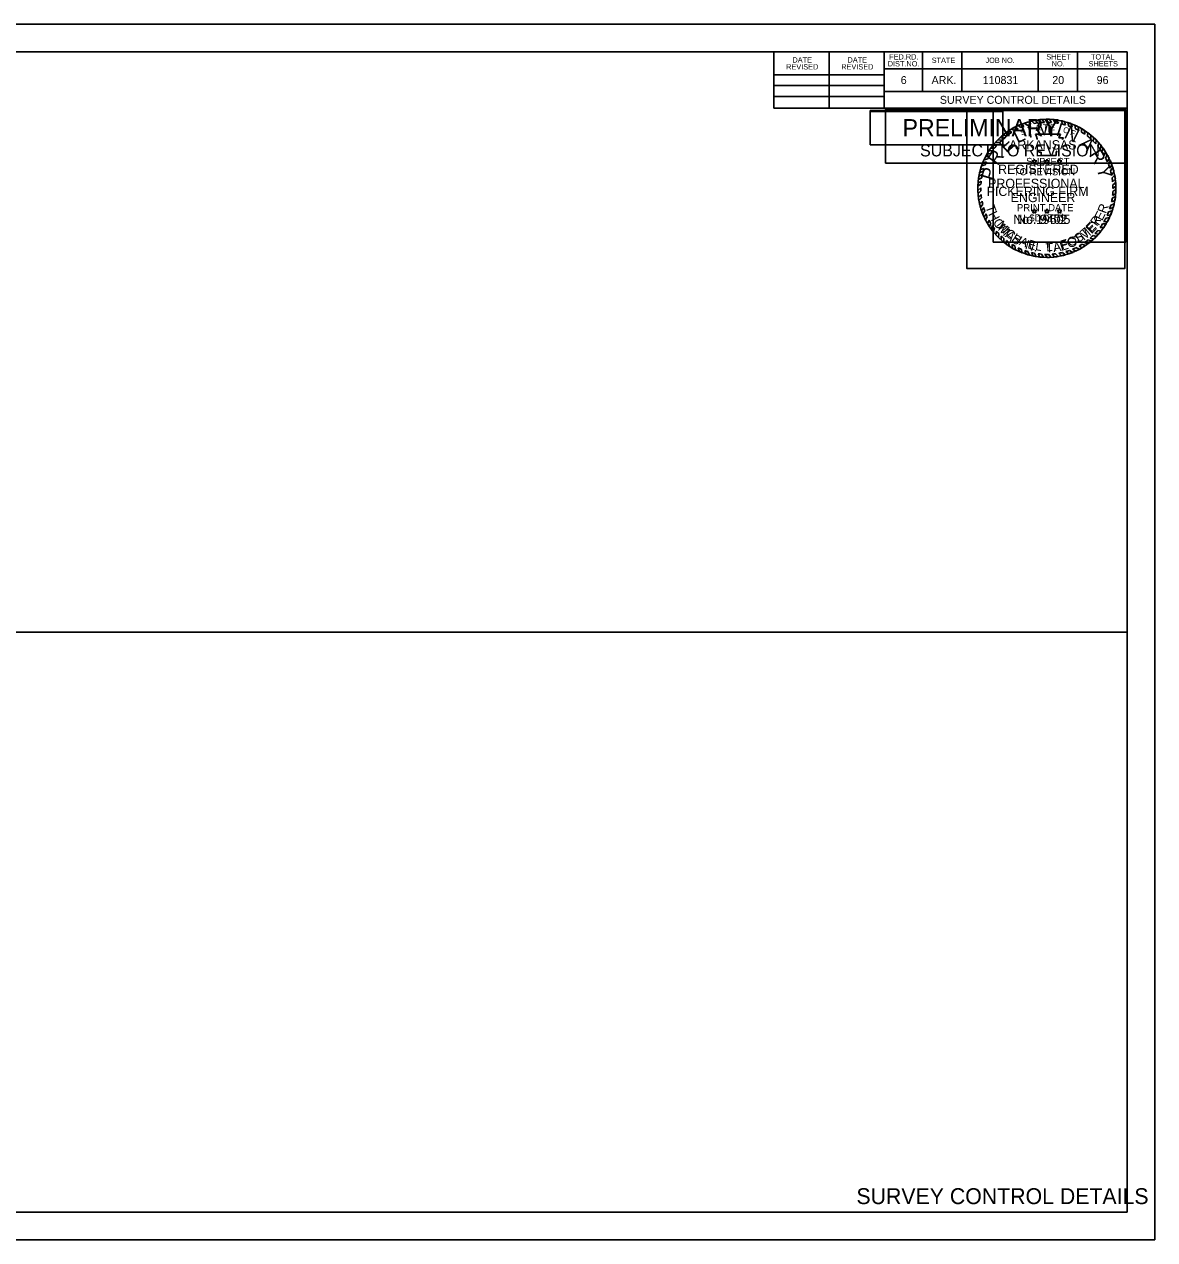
# Model space of a CAD drawing. Extents: x -0.29 to 1.42, y 0 to 0.92.
# Drawn here: x 0.564 to 1.417, y 0 to 0.917 of the extents above; entities that cross this region are included whole.
import ezdxf

# ---------------------------------------------------------------- set-up
doc = ezdxf.new("R2010")
doc.units = 0
for name, color, linetype in [('DSN_DRFT_Guideline-No-Plot', 7, 'Continuous'), ('SHET_Annotations', 7, 'Continuous'), ('SHET_Border-Lines', 7, 'Continuous'), ('SHET_Border-Text', 7, 'Continuous'), ('SHET_Stamp-Prelim', 7, 'Continuous'), ('SHET_Stamp-Seal', 7, 'Continuous'), ('STAMP_PE DIG SIG', 7, 'Continuous'), ('STAMP_PE_BACKGROUND', 7, 'Continuous'), ('STAMP_PE_FOSTER', 7, 'Continuous'), ('STAMP_PE_SEAL-INFO', 7, 'Continuous'), ('STAMP_PE_TAEGTMEYER', 7, 'Continuous'), ('STAMP_PRELIMINARY', 7, 'Continuous')]:
    doc.layers.add(name, color=color, linetype=linetype)

msp = doc.modelspace()

# ---------------------------------------------------------------- linework, layer by layer
at = {"layer": 'DSN_DRFT_Guideline-No-Plot'}
msp.add_lwpolyline([(0, 0), (1.41667, 0), (1.41667, 0.91667), (0, 0.91667)], close=True, dxfattribs=at)
at = {"layer": 'SHET_Border-Lines'}
for p, q in [((1.12962, 0.85338), (1.12962, 0.89583)), ((1.17114, 0.85338), (1.17114, 0.89583)), ((1.21266, 0.89583), (1.21266, 0.85338)), ((1.24173, 0.89583), (1.24173, 0.86601)), ((1.27123, 0.89583), (1.27123, 0.86601)), ((1.32894, 0.89583), (1.32894, 0.86601)), ((1.35843, 0.89583), (1.35843, 0.86601)), ((1.39583, 0.8832), (1.21266, 0.8832)), ((1.39583, 0.88329), (1.39583, 0.88329)), ((1.12962, 0.87856), (1.21266, 0.87856)), ((1.12962, 0.87057), (1.21266, 0.87057)), ((1.12962, 0.86223), (1.21266, 0.86223)), ((1.39583, 0.86601), (1.21266, 0.86601)), ((1.22524, 0.86601), (1.39583, 0.86601)), ((1.39583, 0.85338), (1.12962, 0.85338)), ((0.02083, 0.45833), (1.39583, 0.45833))]:
    msp.add_line(p, q, dxfattribs=at)
for points in [[(0.02083, 0.02083), (1.39583, 0.02083), (1.39583, 0.89583), (0.02083, 0.89583)], [(1.12962, 0.85338), (1.39583, 0.85338), (1.39583, 0.89583), (1.12962, 0.89583)]]:
    msp.add_lwpolyline(points, close=True, dxfattribs=at)
at = {"layer": 'SHET_Stamp-Prelim'}
msp.add_lwpolyline([(1.21366, 0.81193), (1.39483, 0.81193), (1.39483, 0.85238), (1.21366, 0.85238)], close=True, dxfattribs=at)
at = {"layer": 'SHET_Stamp-Seal'}
msp.add_line((1.34483, 0.80238), (1.34483, 0.80238), dxfattribs=at)
msp.add_lwpolyline([(1.29483, 0.75238), (1.39483, 0.75238), (1.39483, 0.85238), (1.29483, 0.85238)], close=True, dxfattribs=at)
at = {"layer": 'STAMP_PE DIG SIG'}
msp.add_lwpolyline([(1.20225, 0.85078), (1.30225, 0.85078), (1.30225, 0.82578), (1.20225, 0.82578)], close=True, dxfattribs=at)
at = {"layer": 'STAMP_PE_BACKGROUND'}
for points in [[(1.20225, 0.85171), (1.30225, 0.85171), (1.30225, 0.82578), (1.20225, 0.82578)], [(1.39417, 0.85171), (1.275, 0.85171), (1.275, 0.73255), (1.39417, 0.73255)]]:
    msp.add_lwpolyline(points, close=True, dxfattribs=at)
at = {"layer": 'STAMP_PE_SEAL-INFO'}
for p, q in [((1.3239, 0.84376), (1.32589, 0.84184)), ((1.32659, 0.8443), (1.32826, 0.84225)), ((1.32947, 0.84471), (1.33104, 0.84257)), ((1.33358, 0.84273), (1.33184, 0.84492)), ((1.33636, 0.84275), (1.33481, 0.84504)), ((1.33892, 0.84264), (1.33748, 0.84501)), ((1.34175, 0.84236), (1.34012, 0.84484)), ((1.34413, 0.84199), (1.34269, 0.84454)), ((1.34727, 0.84133), (1.3463, 0.8439)), ((1.34951, 0.84073), (1.34862, 0.84335)), ((1.30423, 0.83485), (1.30678, 0.8337)), ((1.30658, 0.83634), (1.30905, 0.83521)), ((1.30874, 0.8377), (1.31115, 0.83645)), ((1.31124, 0.8391), (1.31383, 0.83784)), ((1.31365, 0.84028), (1.31583, 0.83875)), ((1.31649, 0.84149), (1.31813, 0.83967)), ((1.31843, 0.8422), (1.32056, 0.84049)), ((1.32173, 0.84322), (1.32334, 0.84128)), ((1.35204, 0.83991), (1.35125, 0.84258)), ((1.35437, 0.83901), (1.35357, 0.84178)), ((1.35695, 0.83787), (1.35638, 0.84064)), ((1.35944, 0.83658), (1.35895, 0.83943)), ((1.36161, 0.83532), (1.36138, 0.83811)), ((1.36403, 0.83372), (1.36386, 0.8366)), ((1.36605, 0.83223), (1.36624, 0.83495)), ((1.2946, 0.82531), (1.29766, 0.82544)), ((1.29653, 0.82761), (1.29944, 0.8274)), ((1.29833, 0.82953), (1.30137, 0.8293)), ((1.3002, 0.83134), (1.30277, 0.83056)), ((1.30212, 0.83302), (1.30508, 0.83246)), ((1.32689, 0.8337), (1.34557, 0.8337)), ((1.32756, 0.83198), (1.32689, 0.8337)), ((1.32814, 0.83032), (1.32756, 0.83198)), ((1.32818, 0.82968), (1.32814, 0.83032)), ((1.34557, 0.8337), (1.34431, 0.83095)), ((1.34431, 0.83095), (1.34785, 0.83095)), ((1.34785, 0.83095), (1.34704, 0.82968)), ((1.36854, 0.83015), (1.36865, 0.83307)), ((1.37029, 0.82851), (1.37068, 0.8313)), ((1.37229, 0.82643), (1.37267, 0.82937)), ((1.37382, 0.82466), (1.37459, 0.82729)), ((1.37563, 0.82233), (1.37639, 0.82512)), ((1.28907, 0.81672), (1.29185, 0.81708)), ((1.29036, 0.81909), (1.29309, 0.8192)), ((1.29173, 0.82133), (1.29462, 0.82151)), ((1.29304, 0.82325), (1.29586, 0.82322)), ((1.32925, 0.82013), (1.32911, 0.82135)), ((1.33101, 0.82013), (1.32925, 0.82013)), ((1.33101, 0.81773), (1.33101, 0.82013)), ((1.34235, 0.81773), (1.33101, 0.81773)), ((1.34243, 0.81962), (1.34235, 0.81773)), ((1.34287, 0.82135), (1.34243, 0.81962)), ((1.37686, 0.82057), (1.37786, 0.82316)), ((1.37858, 0.81779), (1.3796, 0.82053)), ((1.3797, 0.81574), (1.38096, 0.81822)), ((1.28527, 0.80705), (1.28794, 0.80799)), ((1.28615, 0.80986), (1.28886, 0.81062)), ((1.28699, 0.81213), (1.28981, 0.81295)), ((1.28802, 0.81455), (1.29082, 0.81513)), ((1.32525, 0.81292), (1.32414, 0.81372)), ((1.32414, 0.81372), (1.32551, 0.81372)), ((1.32482, 0.81161), (1.32525, 0.81292)), ((1.32593, 0.81242), (1.32482, 0.81161)), ((1.32551, 0.81372), (1.32593, 0.81503)), ((1.32593, 0.81503), (1.32635, 0.81372)), ((1.32704, 0.81161), (1.32593, 0.81242)), ((1.32635, 0.81372), (1.32772, 0.81372)), ((1.32772, 0.81372), (1.32662, 0.81292)), ((1.32662, 0.81292), (1.32704, 0.81161)), ((1.33473, 0.81292), (1.33362, 0.81372)), ((1.33362, 0.81372), (1.33499, 0.81372)), ((1.33431, 0.81161), (1.33473, 0.81292)), ((1.33542, 0.81242), (1.33431, 0.81161)), ((1.33499, 0.81372), (1.33542, 0.81503)), ((1.33542, 0.81503), (1.33584, 0.81372)), ((1.33652, 0.81161), (1.33542, 0.81242)), ((1.33584, 0.81372), (1.33721, 0.81372)), ((1.33721, 0.81372), (1.3361, 0.81292)), ((1.3361, 0.81292), (1.33652, 0.81161)), ((1.34422, 0.81292), (1.34311, 0.81372)), ((1.34311, 0.81372), (1.34448, 0.81372)), ((1.34379, 0.81161), (1.34422, 0.81292)), ((1.3449, 0.81242), (1.34379, 0.81161)), ((1.34448, 0.81372), (1.3449, 0.81503)), ((1.3449, 0.81503), (1.34533, 0.81372)), ((1.34601, 0.81161), (1.3449, 0.81242)), ((1.34533, 0.81372), (1.3467, 0.81372)), ((1.3467, 0.81372), (1.34559, 0.81292)), ((1.34559, 0.81292), (1.34601, 0.81161)), ((1.38099, 0.81304), (1.38225, 0.81575)), ((1.38177, 0.81115), (1.38325, 0.81358)), ((1.38286, 0.80809), (1.38437, 0.81074)), ((1.38346, 0.80605), (1.3851, 0.80858)), ((1.28592, 0.7984), (1.28348, 0.79683)), ((1.28625, 0.80084), (1.28376, 0.79959)), ((1.28672, 0.8034), (1.28412, 0.80201)), ((1.28469, 0.80477), (1.28732, 0.80585)), ((1.38421, 0.80293), (1.38599, 0.80543)), ((1.38459, 0.80081), (1.38657, 0.80278)), ((1.38496, 0.79796), (1.38704, 0.79984)), ((1.28571, 0.79603), (1.28336, 0.79459)), ((1.28562, 0.79327), (1.28336, 0.7914)), ((1.28566, 0.791), (1.28347, 0.78918)), ((1.38493, 0.78764), (1.38735, 0.78907)), ((1.38514, 0.79563), (1.38732, 0.79726)), ((1.38515, 0.79047), (1.38749, 0.79202)), ((1.38521, 0.79273), (1.38748, 0.79453)), ((1.28584, 0.78823), (1.28377, 0.78624)), ((1.28613, 0.78583), (1.28416, 0.78375)), ((1.28657, 0.78327), (1.28468, 0.78122)), ((1.2871, 0.78093), (1.28535, 0.77861)), ((1.38354, 0.78015), (1.38617, 0.78128)), ((1.38414, 0.78268), (1.38668, 0.78377)), ((1.38465, 0.78547), (1.38712, 0.7867)), ((1.28779, 0.77843), (1.28614, 0.7761)), ((1.28857, 0.77607), (1.287, 0.77377)), ((1.2895, 0.77369), (1.28804, 0.77133)), ((1.29046, 0.77154), (1.28919, 0.76897)), ((1.32525, 0.77545), (1.32414, 0.77625)), ((1.32414, 0.77625), (1.32551, 0.77625)), ((1.32482, 0.77414), (1.32525, 0.77545)), ((1.32593, 0.77495), (1.32482, 0.77414)), ((1.32551, 0.77625), (1.32593, 0.77755)), ((1.32593, 0.77755), (1.32635, 0.77625)), ((1.32704, 0.77414), (1.32593, 0.77495)), ((1.32635, 0.77625), (1.32772, 0.77625)), ((1.32772, 0.77625), (1.32662, 0.77545)), ((1.32662, 0.77545), (1.32704, 0.77414)), ((1.33473, 0.77545), (1.33362, 0.77625)), ((1.33362, 0.77625), (1.33499, 0.77625)), ((1.33431, 0.77414), (1.33473, 0.77545)), ((1.33542, 0.77495), (1.33431, 0.77414)), ((1.33499, 0.77625), (1.33542, 0.77755)), ((1.33542, 0.77755), (1.33584, 0.77625)), ((1.33652, 0.77414), (1.33542, 0.77495)), ((1.33584, 0.77625), (1.33721, 0.77625)), ((1.33721, 0.77625), (1.3361, 0.77545)), ((1.3361, 0.77545), (1.33652, 0.77414)), ((1.34422, 0.77545), (1.34311, 0.77625)), ((1.34311, 0.77625), (1.34448, 0.77625)), ((1.34379, 0.77414), (1.34422, 0.77545)), ((1.3449, 0.77495), (1.34379, 0.77414)), ((1.34448, 0.77625), (1.3449, 0.77755)), ((1.3449, 0.77755), (1.34533, 0.77625)), ((1.34601, 0.77414), (1.3449, 0.77495)), ((1.34533, 0.77625), (1.3467, 0.77625)), ((1.3467, 0.77625), (1.34559, 0.77545)), ((1.34559, 0.77545), (1.34601, 0.77414)), ((1.37987, 0.77052), (1.38259, 0.7709)), ((1.38077, 0.7724), (1.38349, 0.77294)), ((1.38196, 0.77527), (1.38466, 0.776)), ((1.38272, 0.77739), (1.38546, 0.77851)), ((1.29177, 0.76898), (1.29071, 0.76625)), ((1.29309, 0.76673), (1.29206, 0.7641)), ((1.29422, 0.76499), (1.29361, 0.7619)), ((1.29579, 0.76281), (1.29522, 0.75984)), ((1.37377, 0.7612), (1.37635, 0.76076)), ((1.37549, 0.7634), (1.37831, 0.76342)), ((1.37739, 0.76616), (1.38005, 0.76613)), ((1.37835, 0.76773), (1.38115, 0.76804)), ((1.29749, 0.7607), (1.297, 0.75779)), ((1.29918, 0.75881), (1.29883, 0.75589)), ((1.30098, 0.75699), (1.30081, 0.75404)), ((1.3029, 0.75524), (1.30289, 0.75229)), ((1.30492, 0.7536), (1.30502, 0.75067)), ((1.30681, 0.75221), (1.30701, 0.74931)), ((1.36385, 0.75208), (1.3663, 0.75103)), ((1.36643, 0.754), (1.36904, 0.75319)), ((1.36794, 0.75525), (1.37057, 0.75453)), ((1.37021, 0.75733), (1.37267, 0.75656)), ((1.37163, 0.75878), (1.37429, 0.75831)), ((1.30919, 0.75063), (1.30953, 0.74777)), ((1.31115, 0.74948), (1.31166, 0.74662)), ((1.31384, 0.74809), (1.31471, 0.74517)), ((1.31592, 0.74714), (1.31688, 0.74429)), ((1.31867, 0.74607), (1.31984, 0.74327)), ((1.32096, 0.74531), (1.32222, 0.74258)), ((1.3238, 0.74454), (1.32498, 0.74194)), ((1.32602, 0.74406), (1.32739, 0.7415)), ((1.32881, 0.74361), (1.33015, 0.74115)), ((1.33125, 0.74334), (1.33278, 0.74095)), ((1.33396, 0.74319), (1.33565, 0.74088)), ((1.33653, 0.74318), (1.33845, 0.74097)), ((1.33942, 0.74333), (1.34124, 0.74121)), ((1.34187, 0.74359), (1.34396, 0.74159)), ((1.34436, 0.74398), (1.34653, 0.74208)), ((1.34711, 0.74456), (1.34922, 0.74274)), ((1.34968, 0.74525), (1.352, 0.74359)), ((1.35243, 0.74616), (1.3549, 0.74466)), ((1.35477, 0.74708), (1.35714, 0.74563)), ((1.35734, 0.74825), (1.36004, 0.74707)), ((1.35962, 0.74944), (1.36195, 0.74814)), ((1.36193, 0.75081), (1.36444, 0.74972))]:
    msp.add_line(p, q, dxfattribs=at)
for radius, start, end in [(0.05208, 99.75254, 102.77648), (0.05208, 93.93815, 96.55172), (0.05208, 87.72979, 90.67067), (0.05208, 81.97315, 84.82355), (0.05208, 75.31251, 77.94263), (0.05208, 123.61993, 126.59063), (0.0498, 121.97456, 125.11001), (0.05208, 117.65441, 120.80988), (0.0498, 115.68692, 119.15827), (0.05208, 111.31242, 114.70259), (0.0498, 110.30864, 113.16588), (0.05208, 105.23389, 109.03519), (0.0498, 104.03521, 107.36155), (0.0498, 98.25799, 101.03289), (0.0498, 92.11016, 95.03666), (0.0498, 85.96279, 88.9097), (0.0498, 79.92642, 82.69597), (0.0498, 73.55748, 76.23144), (0.05208, 69.60611, 72.30577), (0.0498, 67.62483, 70.50398), (0.05208, 63.13288, 66.2704), (0.0498, 61.15575, 64.37837), (0.05208, 56.90029, 60.09423), (0.0498, 54.92383, 58.27016), (0.05208, 50.3492, 53.71593), (0.05208, 141.60556, 144.44865), (0.0498, 139.30101, 142.58729), (0.05208, 135.40208, 138.30314), (0.0498, 133.13306, 136.25623), (0.05208, 129.73259, 132.53764), (0.0498, 127.52969, 130.96829), (0.0498, 48.30163, 52.03953), (0.0498, 42.22116, 45.55119), (0.05208, 44.3405, 47.39292), (0.05208, 38.12472, 41.23157), (0.05208, 152.86398, 155.51889), (0.05208, 147.00719, 149.89904), (0.0498, 151.03153, 153.57304), (0.0498, 145.01972, 148.21036), (0.0498, 36.13503, 39.53106), (0.0498, 29.90321, 33.66454), (0.05208, 31.96138, 35.42937), (0.05208, 25.93909, 29.01247), (0.05208, 164.3068, 166.89395), (0.05208, 158.40766, 161.07015), (0.0498, 162.43309, 165.00133), (0.0498, 156.34018, 159.23194), (0.0498, 23.77322, 27.22114), (0.0498, 17.68022, 21.42509), (0.05208, 19.95381, 23.31409), (0.05208, 13.84205, 17.44468), (0.05208, 170.0003, 172.68778), (0.0498, 173.73, 176.47337), (0.0498, 167.90481, 170.90393), (0.0498, 11.54445, 15.23639), (0.0498, 5.7599, 9.06056), (0.05208, 7.58519, 10.86211), (0.05208, 175.74093, 178.2066), (0.05208, 181.72508, 184.16255), (0.0498, 179.64537, 182.26333), (0.0498, 353.86319, 357.12742), (0.0498, 359.73289, 3.06392), (0.05208, 1.72155, 4.72681), (0.05208, 355.71562, 358.95694), (0.05208, 187.42037, 190.19271), (0.05208, 193.03695, 195.99732), (0.0498, 185.45389, 188.23401), (0.0498, 191.22736, 193.98583), (0.0498, 341.77699, 345.09248), (0.0498, 348.07782, 351.34355), (0.05208, 343.89247, 347.03502), (0.05208, 349.83047, 353.08845), (0.05208, 198.89671, 201.62812), (0.0498, 196.96751, 199.83526), (0.05208, 204.54793, 207.43282), (0.0498, 202.77613, 205.47915), (0.0498, 329.55488, 333.20757), (0.0498, 335.6038, 339.18578), (0.05208, 331.40371, 334.93315), (0.05208, 337.38367, 340.99332), (0.05208, 210.86355, 213.65709), (0.0498, 208.78826, 211.79343), (0.05208, 216.61154, 219.49098), (0.0498, 214.18375, 217.27474), (0.0498, 316.65308, 320.37109), (0.0498, 323.58513, 327.44069), (0.05208, 325.44052, 328.98725), (0.05208, 222.47995, 225.38008), (0.0498, 220.39088, 223.30564), (0.05208, 228.36648, 231.34802), (0.0498, 226.24938, 229.24068), (0.0498, 232.22904, 234.93361), (0.0498, 304.82299, 308.51428), (0.05208, 306.37206, 310.20799), (0.0498, 310.77436, 314.31605), (0.05208, 312.45177, 315.66328), (0.05208, 318.28455, 321.80429), (0.05208, 234.29502, 236.94517), (0.0498, 238.22227, 240.83529), (0.05208, 240.1977, 242.86128), (0.0498, 244.32043, 246.94859), (0.05208, 246.57598, 249.15579), (0.0498, 250.34912, 253.12157), (0.05208, 252.59667, 255.32518), (0.0498, 256.50505, 259.11916), (0.0498, 262.37828, 265.20115), (0.0498, 268.3215, 271.27698), (0.0498, 274.61565, 277.44863), (0.0498, 280.34588, 283.58137), (0.05208, 282.31994, 285.37019), (0.0498, 286.64233, 289.97826), (0.05208, 288.57086, 291.97334), (0.0498, 292.87452, 296.11851), (0.05208, 294.64808, 298.21662), (0.0498, 299.07679, 302.17235), (0.05208, 300.62101, 303.87026), (0.05208, 258.44328, 261.13983), (0.05208, 264.19784, 267.10092), (0.05208, 270.25484, 273.33609), (0.05208, 276.42389, 279.43574)]:
    msp.add_arc((1.33542, 0.79296), radius, start, end, dxfattribs=at)
at = {"layer": 'STAMP_PRELIMINARY'}
msp.add_circle((1.33542, 0.79296), 0.05208, dxfattribs=at)

# ---------------------------------------------------------------- texts
at = {"layer": 'SHET_Annotations'}
for s, height, p in [('6', 0.006, (1.22524, 0.87161)), ('ARK.', 0.006, (1.24847, 0.87161)), ('110831', 0.006, (1.28706, 0.87161)), ('20', 0.006, (1.33949, 0.87161)), ('96', 0.006, (1.37292, 0.87165)), ('SURVEY CONTROL DETAILS', 0.006, (1.25474, 0.8567)), ('SURVEY CONTROL DETAILS', 0.012, (1.19181, 0.02683))]:
    msp.add_text(s, height=height, dxfattribs=at).set_placement(p)
at = {"layer": 'SHET_Border-Text'}
for s, p in [('DATE', (1.14358, 0.8878)), ('DATE', (1.1851, 0.8878)), ('FED.RD.', (1.21651, 0.89012)), ('STATE', (1.24854, 0.88752)), ('JOB NO.', (1.2891, 0.88752)), ('SHEET', (1.33496, 0.89012)), ('TOTAL', (1.36864, 0.89012)), ('REVISED', (1.13885, 0.8826)), ('REVISED', (1.18037, 0.8826)), ('DIST.NO.', (1.21541, 0.88492)), ('NO.', (1.33903, 0.88492)), ('SHEETS', (1.36685, 0.88492))]:
    msp.add_text(s, height=0.004, dxfattribs=at).set_placement(p)
at = {"layer": 'SHET_Stamp-Prelim'}
for s, height, p in [('PRELIMINARY', 0.013, (1.22663, 0.83215)), ('SUBJECT TO REVISION', 0.009, (1.23978, 0.81704))]:
    msp.add_text(s, height=height, dxfattribs=at).set_placement(p)
at = {"layer": 'STAMP_PE_FOSTER'}
msp.add_text('No. 9402', height=0.006983, dxfattribs=at).set_placement((1.31299, 0.76613))
for s, rotation, p in [('R', 54.5031, (1.37298, 0.76398)), ('M', 308.33902, (1.29696, 0.76515)), ('I', 314.18423, (1.30141, 0.75992)), ('C', 319.87327, (1.30339, 0.75794)), ('T', 39.41938, (1.36415, 0.7552)), ('E', 46.96131, (1.36894, 0.75939)), ('H', 327.72349, (1.30858, 0.75383)), ('A', 335.72761, (1.31406, 0.75058)), ('E', 343.5779, (1.32042, 0.74795)), ('L', 350.81148, (1.32633, 0.7464)), ('L', 1.26658, (1.33493, 0.74552)), ('F', 15.86908, (1.34679, 0.7469)), ('O', 23.71897, (1.35262, 0.74873)), ('S', 31.72336, (1.35883, 0.75169)), ('.', 6.80354, (1.34078, 0.74585))]:
    msp.add_text(s, height=0.0067, rotation=rotation, dxfattribs=at).set_placement(p)
at = {"layer": 'STAMP_PE_SEAL-INFO'}
for s, rotation, p in [('S', 23.5541, (1.31642, 0.83265)), ('T', 16.311, (1.32157, 0.83473)), ('A', 9.0679, (1.32695, 0.83614)), ('T', 1.82479, (1.33246, 0.83687)), ('E', 355.20019, (1.33754, 0.83691)), ('O', 342.25065, (1.34719, 0.83537)), ('F', 335.00755, (1.35258, 0.83348))]:
    msp.add_text(s, height=0.00436, rotation=rotation, dxfattribs=at).set_placement(p)
for s, height, p in [('ARKANSAS', 0.006983, (1.30688, 0.82228)), ('REGISTERED', 0.006983, (1.29864, 0.80381)), ('PROFESSIONAL', 0.0069834, (1.29111, 0.79319)), ('ENGINEER', 0.006983, (1.30809, 0.78256))]:
    msp.add_text(s, height=height, dxfattribs=at).set_placement(p)
at = {"layer": 'STAMP_PE_TAEGTMEYER'}
for s, rotation, p in [('T', 289.64597, (1.28902, 0.77905)), ('R', 69.57001, (1.3798, 0.77349)), ('H', 296.73386, (1.29103, 0.77355)), ('Y', 53.99864, (1.37328, 0.76275)), ('E', 63.0984, (1.37702, 0.76801)), ('O', 303.77078, (1.29434, 0.76736)), ('M', 314.20329, (1.298, 0.76205)), ('M', 39.30005, (1.36334, 0.75329)), ('E', 46.80938, (1.36915, 0.7582)), ('A', 321.0594, (1.30337, 0.75666)), ('S', 327.82385, (1.30799, 0.75306)), ('N', 344.27273, (1.31858, 0.74744)), ('T', 3.00609, (1.33466, 0.74447)), ('A', 8.98261, (1.34051, 0.74478)), ('E', 17.68363, (1.34631, 0.74565)), ('G', 23.30524, (1.35218, 0.7475)), ('T', 31.46601, (1.35832, 0.75025)), ('.', 350.64643, (1.32536, 0.74559))]:
    msp.add_text(s, height=0.00698, rotation=rotation, dxfattribs=at).set_placement(p)
msp.add_text('No. 19605', height=0.006983, dxfattribs=at).set_placement((1.31006, 0.76613))
at = {"layer": 'STAMP_PRELIMINARY'}
for s, rotation, p in [('L', 25.51305, (1.31312, 0.82664)), ('I', 12.52485, (1.32166, 0.83088)), ('M', 3.10738, (1.32779, 0.83261)), ('I', 342.31637, (1.34158, 0.83298)), ('N', 333.9382, (1.34777, 0.83145)), ('E', 42.35784, (1.30484, 0.8192)), ('A', 315.65789, (1.35913, 0.82572)), ('R', 56.22922, (1.29838, 0.80952)), ('R', 301.38306, (1.36677, 0.81838)), ('P', 73.91301, (1.29531, 0.79822)), ('Y', 283.25926, (1.37286, 0.8084))]:
    msp.add_text(s, height=0.01006, rotation=rotation, dxfattribs=at).set_placement(p)
for s, height, p in [('SUBJECT', 0.005363, (1.31977, 0.81056)), ('TO REVISION', 0.0053633, (1.31047, 0.80282)), ('PICKERING FIRM', 0.0069834, (1.29001, 0.78717)), ('PRINT DATE', 0.005363, (1.31283, 0.77573)), ('$DATE$', 0.005363, (1.3222, 0.768))]:
    msp.add_text(s, height=height, dxfattribs=at).set_placement(p)

doc.saveas('drawing.dxf')
